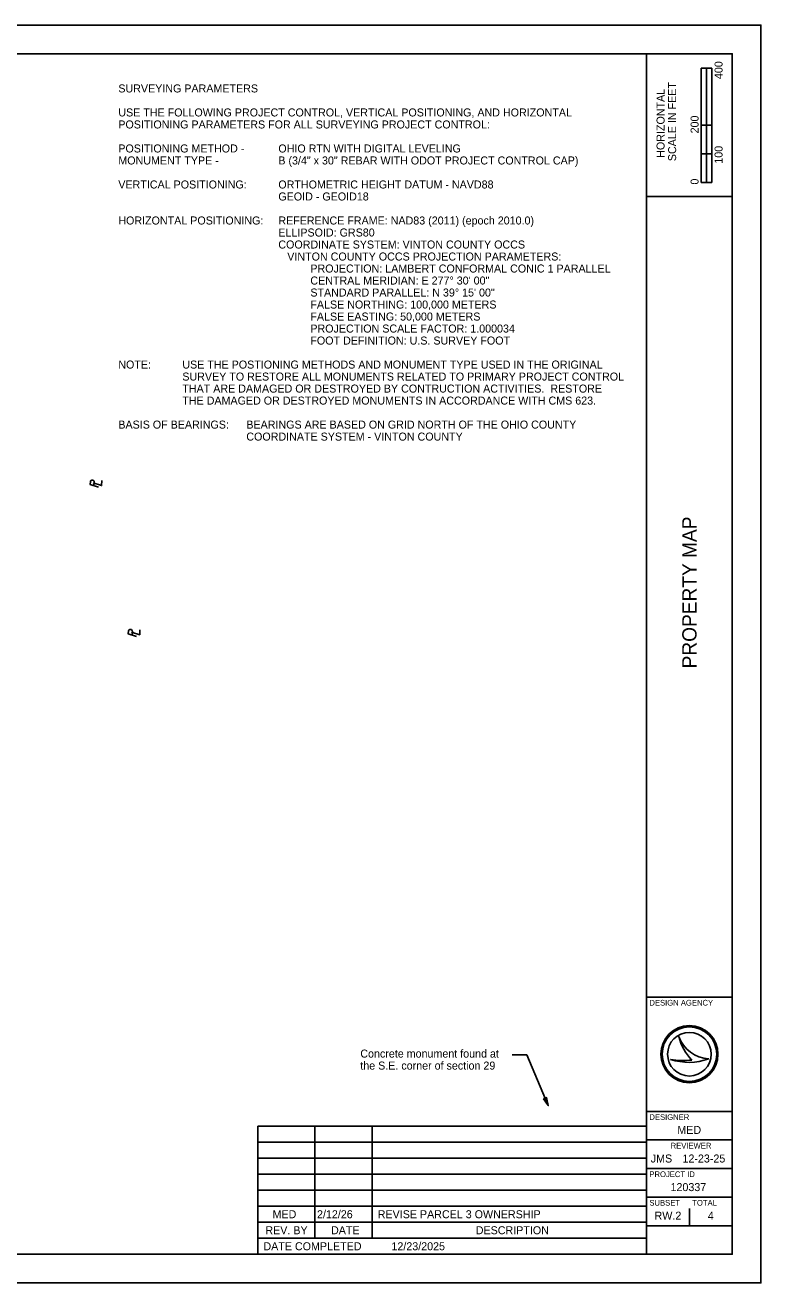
# Model space of a CAD drawing. Extents: x 160408 to 202243, y 235663 to 338930.
# Drawn here: x 197454 to 200029, y 334530 to 338930 of the extents above; entities that cross this region are included whole.
import ezdxf

# ---------------------------------------------------------------- set-up
doc = ezdxf.new("R2010")
doc.units = 0
for name, color, linetype in [('_CIVIL_CONSTRUCTION', 7, 'Continuous'), ('GE_P_Alignment', 7, 'Continuous'), ('GE_P_Alignment_100_Bearings', 7, 'Continuous'), ('PF_X_Ground_Line', 7, 'Continuous'), ('SC_Scratch1', 7, 'Continuous')]:
    doc.layers.add(name, color=color, linetype=linetype)

msp = doc.modelspace()

# ---------------------------------------------------------------- linework, layer by layer
at = {"layer": '_CIVIL_CONSTRUCTION'}
msp.add_lwpolyline([(193229, 334529.6), (200029, 334529.6), (200029, 338929.6), (193229, 338929.6)], close=True, dxfattribs=at)
at = {"layer": 'GE_P_Alignment'}
for p, q in [((199820.3, 338379.6), (199820.3, 338779.6)), ((199857.8, 338779.6), (199820.3, 338779.6)), ((199820.3, 338579.6), (199820.3, 338779.6)), ((199820.3, 338779.6), (199839, 338779.6)), ((199839, 338779.6), (199839.1, 338779.6)), ((199839.1, 338779.6), (199839.1, 338579.6)), ((199857.8, 338779.6), (199857.8, 338379.6)), ((199839.1, 338579.6), (199820.3, 338579.6)), ((199857.6, 338579.6), (199839, 338579.6)), ((199839, 338579.6), (199839, 338479.6)), ((199857.6, 338479.6), (199857.6, 338579.6)), ((199839, 338479.6), (199820.3, 338479.6)), ((199820.3, 338479.6), (199820.3, 338379.6)), ((199839, 338479.6), (199857.6, 338479.6)), ((199839, 338379.6), (199839, 338479.6)), ((199857.8, 338379.6), (199820.3, 338379.6)), ((199820.3, 338379.6), (199839, 338379.6)), ((199742.5, 335391.5), (199742.5, 335391.5)), ((199779, 335329.6), (199779, 335329.6)), ((199712.4, 335311.5), (199712.4, 335311.5)), ((199846.4, 335313.3), (199846.4, 335313.3)), ((199779, 334729.6), (199779, 334789.6))]:
    msp.add_line(p, q, dxfattribs=at)
for radius in [100, 95.4, 95.4, 76.4]:
    msp.add_circle((199779, 335329.6), radius, dxfattribs=at)
for centre, radius, start, end in [((199852.2, 335429.1), 116, 198.9257, 198.9319), ((199898.3, 335423.6), 159.1, 191.6379, 191.6421), ((199852.2, 335429.1), 116, 198.9319, 267.1657), ((199898.3, 335423.6), 159.1, 191.6421, 226.0947), ((199776.9, 335503.6), 202.6, 251.4576, 290.0832), ((199758.6, 335560.5), 253.2, 259.4964, 259.4995), ((199776.9, 335503.6), 202.6, 251.4527, 251.4576), ((199758.6, 335560.5), 253.2, 259.4995, 276.6672)]:
    msp.add_arc(centre, radius, start, end, dxfattribs=at)
at = {"layer": 'GE_P_Alignment_100_Bearings'}
for p, q in [((199629, 334629.6), (199629, 338829.6)), ((199629, 338329.6), (199929, 338329.6)), ((199629, 335529.6), (199929, 335529.6)), ((199629, 335129.6), (199929, 335129.6)), ((199629, 335029.6), (199929, 335029.6)), ((199629, 334929.6), (199929, 334929.6)), ((199629, 334829.6), (199929, 334829.6)), ((199629, 334729.6), (199929, 334729.6))]:
    msp.add_line(p, q, dxfattribs=at)
msp.add_lwpolyline([(193529, 338829.6), (199929, 338829.6), (199929, 334629.6), (193529, 334629.6)], close=True, dxfattribs=at)
at = {"layer": 'PF_X_Ground_Line'}
for p, q in [((197695.3, 337318.1), (197696.2, 337331)), ((197702.1, 337325.6), (197702.1, 337325.6)), ((197829, 336795.5), (197829.7, 336808.4)), ((197835.7, 336803.2), (197835.7, 336803.2))]:
    msp.add_line(p, q, dxfattribs=at)
for points in [[(197710.9, 337312.8), (197681.9, 337322.6), (197682.6, 337333)], [(197692.7, 337329), (197721.7, 337319), (197722.9, 337336.4)], [(197844.6, 336790.4), (197815.5, 336799.9), (197816.1, 336810.2)], [(197826.2, 336806.4), (197855.3, 336796.8), (197856.3, 336814.2)]]:
    msp.add_lwpolyline(points, dxfattribs=at)
for centre, start, end in [((197689.4, 337331.4), 356.4432, 167.3003), ((197822.8, 336808.8), 357.2657, 168.1228)]:
    msp.add_arc(centre, 6.9, start, end, dxfattribs=at)
at = {"layer": 'SC_Scratch1'}
for p, q in [((199209.7, 335327.3), (199159.2, 335327.3)), ((199285, 335149.8), (199209.7, 335327.3)), ((198268.3, 335077.6), (198268.3, 334629.6)), ((198268.3, 335077.6), (199629, 335077.6)), ((198468.3, 335077.6), (198468.3, 334685.6)), ((198668.3, 335077.6), (198668.3, 334685.6)), ((198268.3, 335021.6), (199629, 335021.6)), ((198268.3, 334965.6), (199629, 334965.6)), ((198268.3, 334909.6), (199629, 334909.6)), ((198268.3, 334853.6), (199629, 334853.6)), ((198268.3, 334797.6), (199629, 334797.6)), ((198268.3, 334741.6), (199629, 334741.6)), ((198268.3, 334685.6), (199629, 334685.6)), ((199629, 334629.6), (199629, 334629.6))]:
    msp.add_line(p, q, dxfattribs=at)
msp.add_lwpolyline([(199268.9, 335173.4), (199279.2, 335177.8), (199285, 335149.8)], close=True, dxfattribs=at)

# ---------------------------------------------------------------- texts
at = {"layer": 'GE_P_Alignment'}
for s, height, p in [('400', 28, (199895, 338740.9)), ('SCALE IN FEET', 28, (199732.5, 338453.7)), ('HORIZONTAL', 28, (199692, 338465.5)), ('200', 28, (199811.1, 338550.9)), ('100', 28, (199895, 338445)), ('0', 28, (199811.1, 338371.9)), ('PROPERTY MAP', 50, (199804, 336679.2))]:
    msp.add_text(s, height=height, rotation=90, dxfattribs=at).set_placement(p)
for s, height, p in [('DESIGN AGENCY', 20, (199639, 335499.6)), ('DESIGNER', 20, (199639, 335099.6)), ('MED', 28, (199736.8, 335050.6)), ('REVIEWER', 20, (199713.3, 334999.6)), ('JMS', 28, (199643.7, 334950.6)), ('12-23-25', 28, (199754.7, 334950.6)), ('PROJECT ID', 20, (199639, 334899.6)), ('120337', 28, (199712.9, 334850.6)), ('SUBSET', 20, (199639, 334799.6)), ('TOTAL', 20, (199789, 334799.6)), ('RW.2', 28, (199657, 334750.6)), ('4', 28, (199843.4, 334750.6))]:
    msp.add_text(s, height=height, dxfattribs=at).set_placement(p)
at = {"layer": 'SC_Scratch1'}
for s, p in [('SURVEYING PARAMETERS', (197780.5, 338694.2)), ('USE THE FOLLOWING PROJECT CONTROL, VERTICAL POSITIONING, AND HORIZONTAL ', (197780.5, 338610.2)), ('POSITIONING PARAMETERS FOR ALL SURVEYING PROJECT CONTROL:', (197780.5, 338568.2)), ('POSITIONING METHOD - ', (197780.5, 338484.2)), ('OHIO RTN WITH DIGITAL LEVELING', (198340.5, 338484.2)), ('MONUMENT TYPE - ', (197780.5, 338442.2)), ('B (3/4" x 30" REBAR WITH ODOT PROJECT CONTROL CAP)', (198340.5, 338442.2)), ('VERTICAL POSITIONING:', (197780.5, 338358.2)), ('ORTHOMETRIC HEIGHT DATUM - NAVD88', (198340.5, 338358.2)), ('GEOID - GEOID18 ', (198340.5, 338316.2)), ('HORIZONTAL POSITIONING:', (197780.5, 338232.2)), ('REFERENCE FRAME: NAD83 (2011) (epoch 2010.0)', (198340.5, 338232.2)), ('ELLIPSOID: GRS80', (198340.5, 338190.2)), ('COORDINATE SYSTEM: VINTON COUNTY OCCS', (198340.5, 338148.2)), ('   VINTON COUNTY OCCS PROJECTION PARAMETERS:', (198340.5, 338106.2)), ('PROJECTION: LAMBERT CONFORMAL CONIC 1 PARALLEL', (198452.5, 338064.2)), ('STANDARD PARALLEL: N 39%%D 15\' 00"', (198452.5, 337980.2)), ('CENTRAL MERIDIAN: E 277%%D 30\' 00"                              ', (198452.5, 338022.2)), ('FALSE NORTHING: 100,000 METERS', (198452.5, 337938.2)), ('FALSE EASTING: 50,000 METERS', (198452.5, 337896.2)), ('PROJECTION SCALE FACTOR: 1.000034', (198452.5, 337854.2)), ('FOOT DEFINITION: U.S. SURVEY FOOT', (198452.5, 337812.2)), ('NOTE:', (197780.5, 337728.2)), ('USE THE POSTIONING METHODS AND MONUMENT TYPE USED IN THE ORIGINAL ', (198004.5, 337728.2)), ('SURVEY TO RESTORE ALL MONUMENTS RELATED TO PRIMARY PROJECT CONTROL', (198004.5, 337686.2)), ('THAT ARE DAMAGED OR DESTROYED BY CONTRUCTION ACTIVITIES.  RESTORE ', (198004.5, 337644.2)), ('THE DAMAGED OR DESTROYED MONUMENTS IN ACCORDANCE WITH CMS 623.', (198004.5, 337602.2)), ('BASIS OF BEARINGS:', (197780.5, 337518.2)), ('BEARINGS ARE BASED ON GRID NORTH OF THE OHIO COUNTY ', (198228.5, 337518.2)), ('COORDINATE SYSTEM - VINTON COUNTY', (198228.5, 337476.2))]:
    msp.add_text(s, height=28, rotation=360, dxfattribs=at).set_placement(p)
for s, p in [('Concrete monument found at', (198627.3, 335317.7)), ('the S.E. corner of section 29', (198627.3, 335275.7)), ('MED', (198320.3, 334755.6)), ('2/12/26', (198475.8, 334755.6)), ('REVISE PARCEL 3 OWNERSHIP', (198688.3, 334755.6)), ('REV. BY', (198295.1, 334699.6)), ('DATE', (198524.9, 334699.6)), ('DESCRIPTION', (199031.4, 334699.6)), ('DATE COMPLETED', (198288.3, 334643.6)), ('12/23/2025', (198736.3, 334643.6))]:
    msp.add_text(s, height=28, dxfattribs=at).set_placement(p)

doc.saveas('drawing.dxf')
